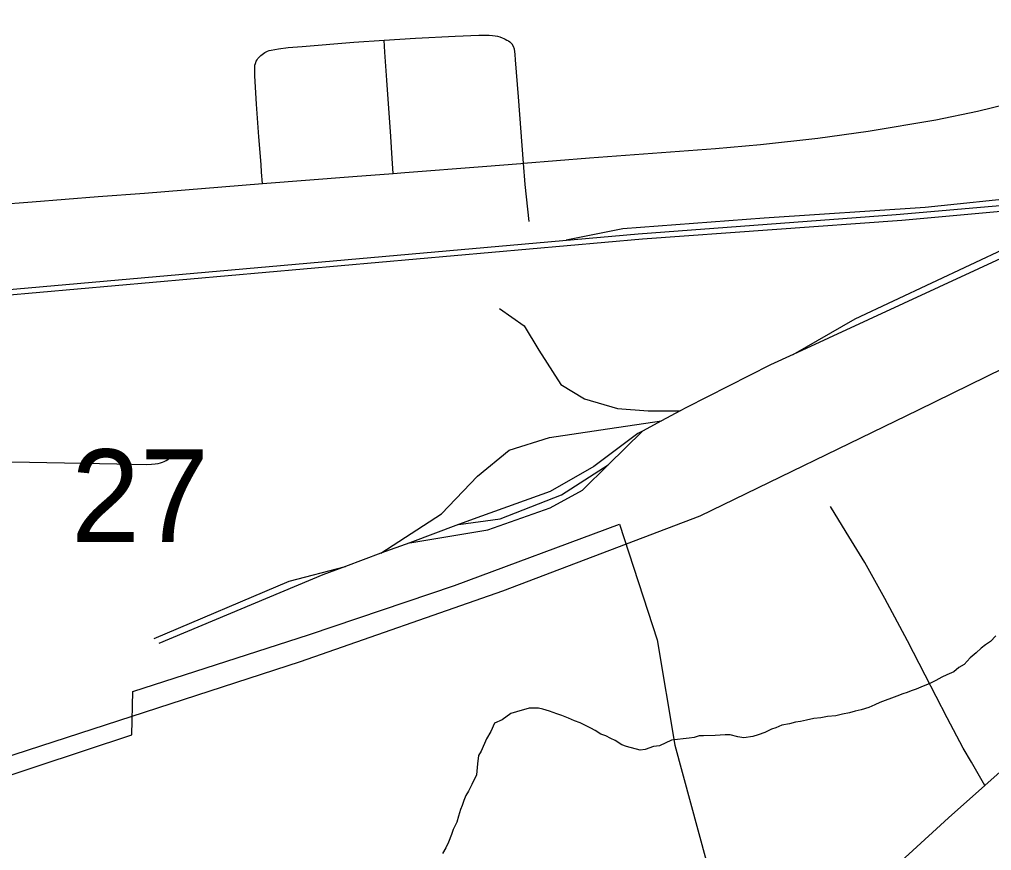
# Model space of a CAD drawing. Extents: x 2.4 to 73.1, y 4.5 to 25.6.
# Drawn here: x 35.2682 to 35.4879, y 22.2401 to 22.428 of the extents above; entities that cross this region are included whole.
import ezdxf

# ---------------------------------------------------------------- set-up
doc = ezdxf.new("R2010")
doc.units = 0
for name, color, linetype in [('GM_X_City_Street', 7, 'Continuous'), ('GM_X_Corporation', 7, 'Continuous'), ('GM_X_County_Road', 7, 'Continuous'), ('GM_X_Minor_River', 7, 'Continuous'), ('GM_X_Rail_Line', 7, 'Continuous'), ('GM_X_Section_Text', 7, 'Continuous')]:
    doc.layers.add(name, color=color, linetype=linetype)

msp = doc.modelspace()

# ---------------------------------------------------------------- linework, layer by layer
at = {"layer": 'GM_X_City_Street'}
for points in [[(35.32186, 22.41892), (35.32204, 22.41919), (35.32247, 22.41968), (35.32272, 22.41991), (35.32299, 22.42014), (35.32329, 22.42036), (35.3236, 22.42055), (35.32426, 22.42086), (35.32463, 22.42098), (35.32504, 22.42108), (35.32669, 22.42137), (35.32887, 22.42166), (35.33205, 22.42195), (35.34372, 22.42289), (35.35057, 22.42332), (35.35769, 22.42377), (35.36665, 22.42427), (35.372, 22.42444), (35.3743, 22.42448), (35.3751, 22.42442), (35.37568, 22.42434), (35.37619, 22.42423), (35.37677, 22.42407), (35.3773, 22.42388), (35.37763, 22.42374), (35.37798, 22.42357), (35.37835, 22.42337), (35.37866, 22.42319), (35.37897, 22.42296), (35.37926, 22.42271), (35.37951, 22.42245)], [(35.35263, 22.39321), (35.35242, 22.39657), (35.35211, 22.40159), (35.3512, 22.41427), (35.35076, 22.42067), (35.35057, 22.42332)], [(35.38335, 22.38238), (35.38244, 22.39072), (35.38207, 22.39551), (35.38092, 22.41056), (35.38031, 22.41893), (35.3802, 22.4201), (35.38012, 22.42082), (35.38004, 22.42133), (35.37984, 22.42193), (35.37951, 22.42245)], [(35.32309, 22.39093), (35.3229, 22.39353), (35.32278, 22.39526), (35.32229, 22.40148), (35.32172, 22.40889), (35.32139, 22.41528), (35.32135, 22.41674), (35.32136, 22.41728), (35.3214, 22.41771), (35.32149, 22.41808), (35.32169, 22.41863), (35.32186, 22.41892)], [(35.25792, 22.32811), (35.27042, 22.32792), (35.29014, 22.32757), (35.29697, 22.32742), (35.29799, 22.32745), (35.29884, 22.32753), (35.29951, 22.32763), (35.30005, 22.32777), (35.30048, 22.32792), (35.30091, 22.3281), (35.3013, 22.32831), (35.30171, 22.32857), (35.30206, 22.32885), (35.30242, 22.32918), (35.30323, 22.33012)], [(35.48639, 22.25486), (35.48331, 22.26011), (35.48143, 22.26331), (35.47782, 22.27017), (35.47284, 22.27982), (35.46888, 22.28756), (35.46376, 22.29713), (35.45921, 22.30523), (35.45504, 22.31214), (35.45147, 22.31795)]]:
    msp.add_lwpolyline(points, dxfattribs=at)
at = {"layer": 'GM_X_Corporation'}
msp.add_lwpolyline([(35.17492, 22.22666), (35.22816, 22.24463), (35.29357, 22.26626), (35.29376, 22.27606), (35.33372, 22.28896), (35.36648, 22.30003), (35.40382, 22.31392), (35.41227, 22.28777), (35.41629, 22.26398), (35.42334, 22.23787)], dxfattribs=at)
at = {"layer": 'GM_X_County_Road'}
for points in [[(35.38207, 22.39551), (35.39698, 22.39673), (35.42545, 22.39886), (35.43566, 22.39978), (35.44862, 22.40119), (35.46, 22.40276), (35.4753, 22.40536), (35.48471, 22.40731), (35.49829, 22.41059), (35.50937, 22.41363), (35.52035, 22.41699), (35.53302, 22.42123), (35.54349, 22.42513), (35.54747, 22.42682)], [(35.35263, 22.39321), (35.35524, 22.39341), (35.37284, 22.39482), (35.38149, 22.39546), (35.38207, 22.39551)], [(35.32309, 22.39093), (35.34348, 22.39251), (35.35263, 22.39321)], [(35.27103, 22.3868), (35.28595, 22.38798), (35.2964, 22.38879), (35.32309, 22.39093)], [(35.23112, 22.38354), (35.23227, 22.38364), (35.26307, 22.38617), (35.27103, 22.3868)], [(35.48639, 22.25486), (35.49116, 22.2591), (35.49579, 22.26322)], [(35.4326, 22.20655), (35.44173, 22.2146), (35.46068, 22.23162), (35.46921, 22.23934), (35.47816, 22.24752), (35.48639, 22.25486)]]:
    msp.add_lwpolyline(points, dxfattribs=at)
at = {"layer": 'GM_X_Minor_River'}
for points in [[(35.48884, 22.28868), (35.48767, 22.28738), (35.48651, 22.28665), (35.48554, 22.28592), (35.48437, 22.28481), (35.48302, 22.2837), (35.48165, 22.28222), (35.48049, 22.28149), (35.47933, 22.28057), (35.47779, 22.27984), (35.47664, 22.27931), (35.47529, 22.27858), (35.47375, 22.27786), (35.47241, 22.27732), (35.47087, 22.2766), (35.46973, 22.27625), (35.46877, 22.2759), (35.46781, 22.27554), (35.46647, 22.275), (35.46263, 22.27358), (35.46148, 22.27304), (35.46014, 22.27251), (35.45841, 22.27198), (35.45708, 22.27163), (35.45574, 22.27129), (35.45421, 22.27095), (35.45268, 22.27061), (35.45078, 22.27046), (35.44925, 22.27012), (35.44773, 22.26997), (35.44601, 22.26964), (35.44467, 22.26929), (35.44353, 22.26913), (35.44219, 22.26878), (35.44047, 22.26845), (35.43913, 22.26791), (35.43817, 22.26756), (35.43663, 22.26683), (35.4351, 22.2663), (35.43395, 22.26595), (35.43185, 22.26563), (35.43053, 22.26585), (35.42883, 22.26627), (35.42769, 22.2663), (35.42541, 22.26617), (35.42275, 22.26605), (35.4218, 22.26607), (35.42065, 22.26572), (35.41951, 22.26556), (35.41551, 22.26509), (35.41282, 22.26383), (35.41148, 22.26367), (35.40957, 22.26296)], [(35.40957, 22.26296), (35.40842, 22.2628), (35.4054, 22.26364), (35.40428, 22.26405), (35.40278, 22.26503), (35.40184, 22.26544), (35.40072, 22.26604), (35.39959, 22.26644), (35.39828, 22.26724), (35.39734, 22.26783), (35.3964, 22.26823), (35.3949, 22.26903), (35.39358, 22.26945), (35.39227, 22.27005), (35.39077, 22.27066), (35.38964, 22.27106), (35.38794, 22.27168), (35.38643, 22.27209), (35.38549, 22.27231), (35.38454, 22.27233), (35.3834, 22.27236), (35.38053, 22.27148), (35.37919, 22.27114), (35.37726, 22.26967), (35.37553, 22.26895), (35.37472, 22.26707), (35.37373, 22.26539), (35.37252, 22.26257), (35.37193, 22.26164), (35.37169, 22.25974), (35.37144, 22.25728), (35.37043, 22.25503), (35.36963, 22.25353), (35.36904, 22.25259), (35.36863, 22.25147), (35.36823, 22.25034), (35.36782, 22.2494), (35.3674, 22.24789), (35.36699, 22.24657), (35.36619, 22.24488), (35.36578, 22.24375), (35.36517, 22.24206), (35.36457, 22.24074), (35.36377, 22.23943)]]:
    msp.add_lwpolyline(points, dxfattribs=at)
at = {"layer": 'GM_X_Rail_Line'}
for p, q in [((35.50277, 22.37995), (35.44302, 22.3523)), ((35.41748, 22.33951), (35.4133, 22.33729)), ((35.4133, 22.33729), (35.40897, 22.33498)), ((35.40123, 22.32735), (35.40897, 22.33498)), ((35.36739, 22.31381), (35.35637, 22.30974)), ((35.35637, 22.30974), (35.34987, 22.30733)), ((35.34987, 22.30733), (35.34183, 22.30436))]:
    msp.add_line(p, q, dxfattribs=at)
for points in [[(35.82164, 22.59015), (35.7317, 22.51311), (35.68063, 22.47119), (35.6569, 22.4528), (35.62443, 22.42927), (35.60819, 22.41858), (35.5899, 22.40687), (35.57922, 22.40255), (35.56658, 22.39916), (35.53966, 22.39361), (35.51911, 22.39033), (35.47287, 22.3855), (35.43649, 22.38313), (35.40454, 22.38067), (35.39176, 22.3781)], [(34.67285, 22.32089), (34.92723, 22.34151), (35.23002, 22.36381), (35.40803, 22.37954), (35.46629, 22.38395), (35.50969, 22.38773), (35.54765, 22.39296), (35.58276, 22.39961), (35.60028, 22.40441), (35.65992, 22.41752), (35.7031, 22.42787), (35.74313, 22.43653), (35.80025, 22.44949), (35.83117, 22.45653), (35.86024, 22.46257), (35.89286, 22.46787), (35.9246, 22.47051), (35.94854, 22.47177), (36.0534, 22.46888), (36.18913, 22.46436), (36.29738, 22.46089)], [(34.67295, 22.31965), (34.92476, 22.34017), (35.23012, 22.36257), (35.40895, 22.37841), (35.46763, 22.38262), (35.50985, 22.38649), (35.54785, 22.39174), (35.58304, 22.3984), (35.60058, 22.4032), (35.6602, 22.41631), (35.70338, 22.42666), (35.74339, 22.43531), (35.80052, 22.44828), (35.83144, 22.45532), (35.86046, 22.46135), (35.89301, 22.46663), (35.92468, 22.46927), (35.94856, 22.47053), (36.05337, 22.46764), (36.18909, 22.46311), (36.29738, 22.45965)], [(35.44302, 22.3523), (35.45704, 22.36032), (35.49167, 22.37666), (35.50277, 22.37995)], [(35.37669, 22.36268), (35.38224, 22.35878), (35.38553, 22.35323), (35.39056, 22.34552), (35.39591, 22.34224), (35.4033, 22.34008), (35.41029, 22.33957), (35.41748, 22.33951)], [(34.97621, 22.1674), (35.33169, 22.28284), (35.3774, 22.29883), (35.42204, 22.31582), (35.47133, 22.33977), (35.51345, 22.36042)], [(35.44302, 22.3523), (35.43793, 22.34994), (35.41892, 22.34028), (35.41748, 22.33951)], [(35.34987, 22.30733), (35.36354, 22.31624), (35.37166, 22.32477), (35.37885, 22.33063), (35.38799, 22.3335), (35.3996, 22.33525), (35.4133, 22.33729)], [(35.40897, 22.33498), (35.40793, 22.33443), (35.39796, 22.32693), (35.3881, 22.32128), (35.37258, 22.31573), (35.36739, 22.31381)], [(35.35637, 22.30974), (35.37402, 22.31264), (35.3881, 22.31758), (35.39539, 22.32158), (35.40123, 22.32735)], [(35.36739, 22.31381), (35.37679, 22.31511), (35.39066, 22.32056), (35.40123, 22.32735)], [(35.2986, 22.28809), (35.32912, 22.30103), (35.34183, 22.30436)], [(35.34183, 22.30436), (35.33672, 22.30247), (35.29963, 22.28696)]]:
    msp.add_lwpolyline(points, dxfattribs=at)

# ---------------------------------------------------------------- texts
at = {"layer": 'GM_X_Section_Text'}
msp.add_text('27', height=0.020928, rotation=0, dxfattribs=at).set_placement((35.27986, 22.30991))

doc.saveas('drawing.dxf')
